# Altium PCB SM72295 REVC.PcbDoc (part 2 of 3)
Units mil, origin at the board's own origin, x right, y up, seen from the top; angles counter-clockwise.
Board outline 8660 x 6340 mil, 6 copper layers (Top Layer, MidLayer1, MidLayer2, MidLayer3, MidLayer4, Bottom Layer), stack 118 mil thick; 253 components, 96 nets, 606 pads, 1472 vias.
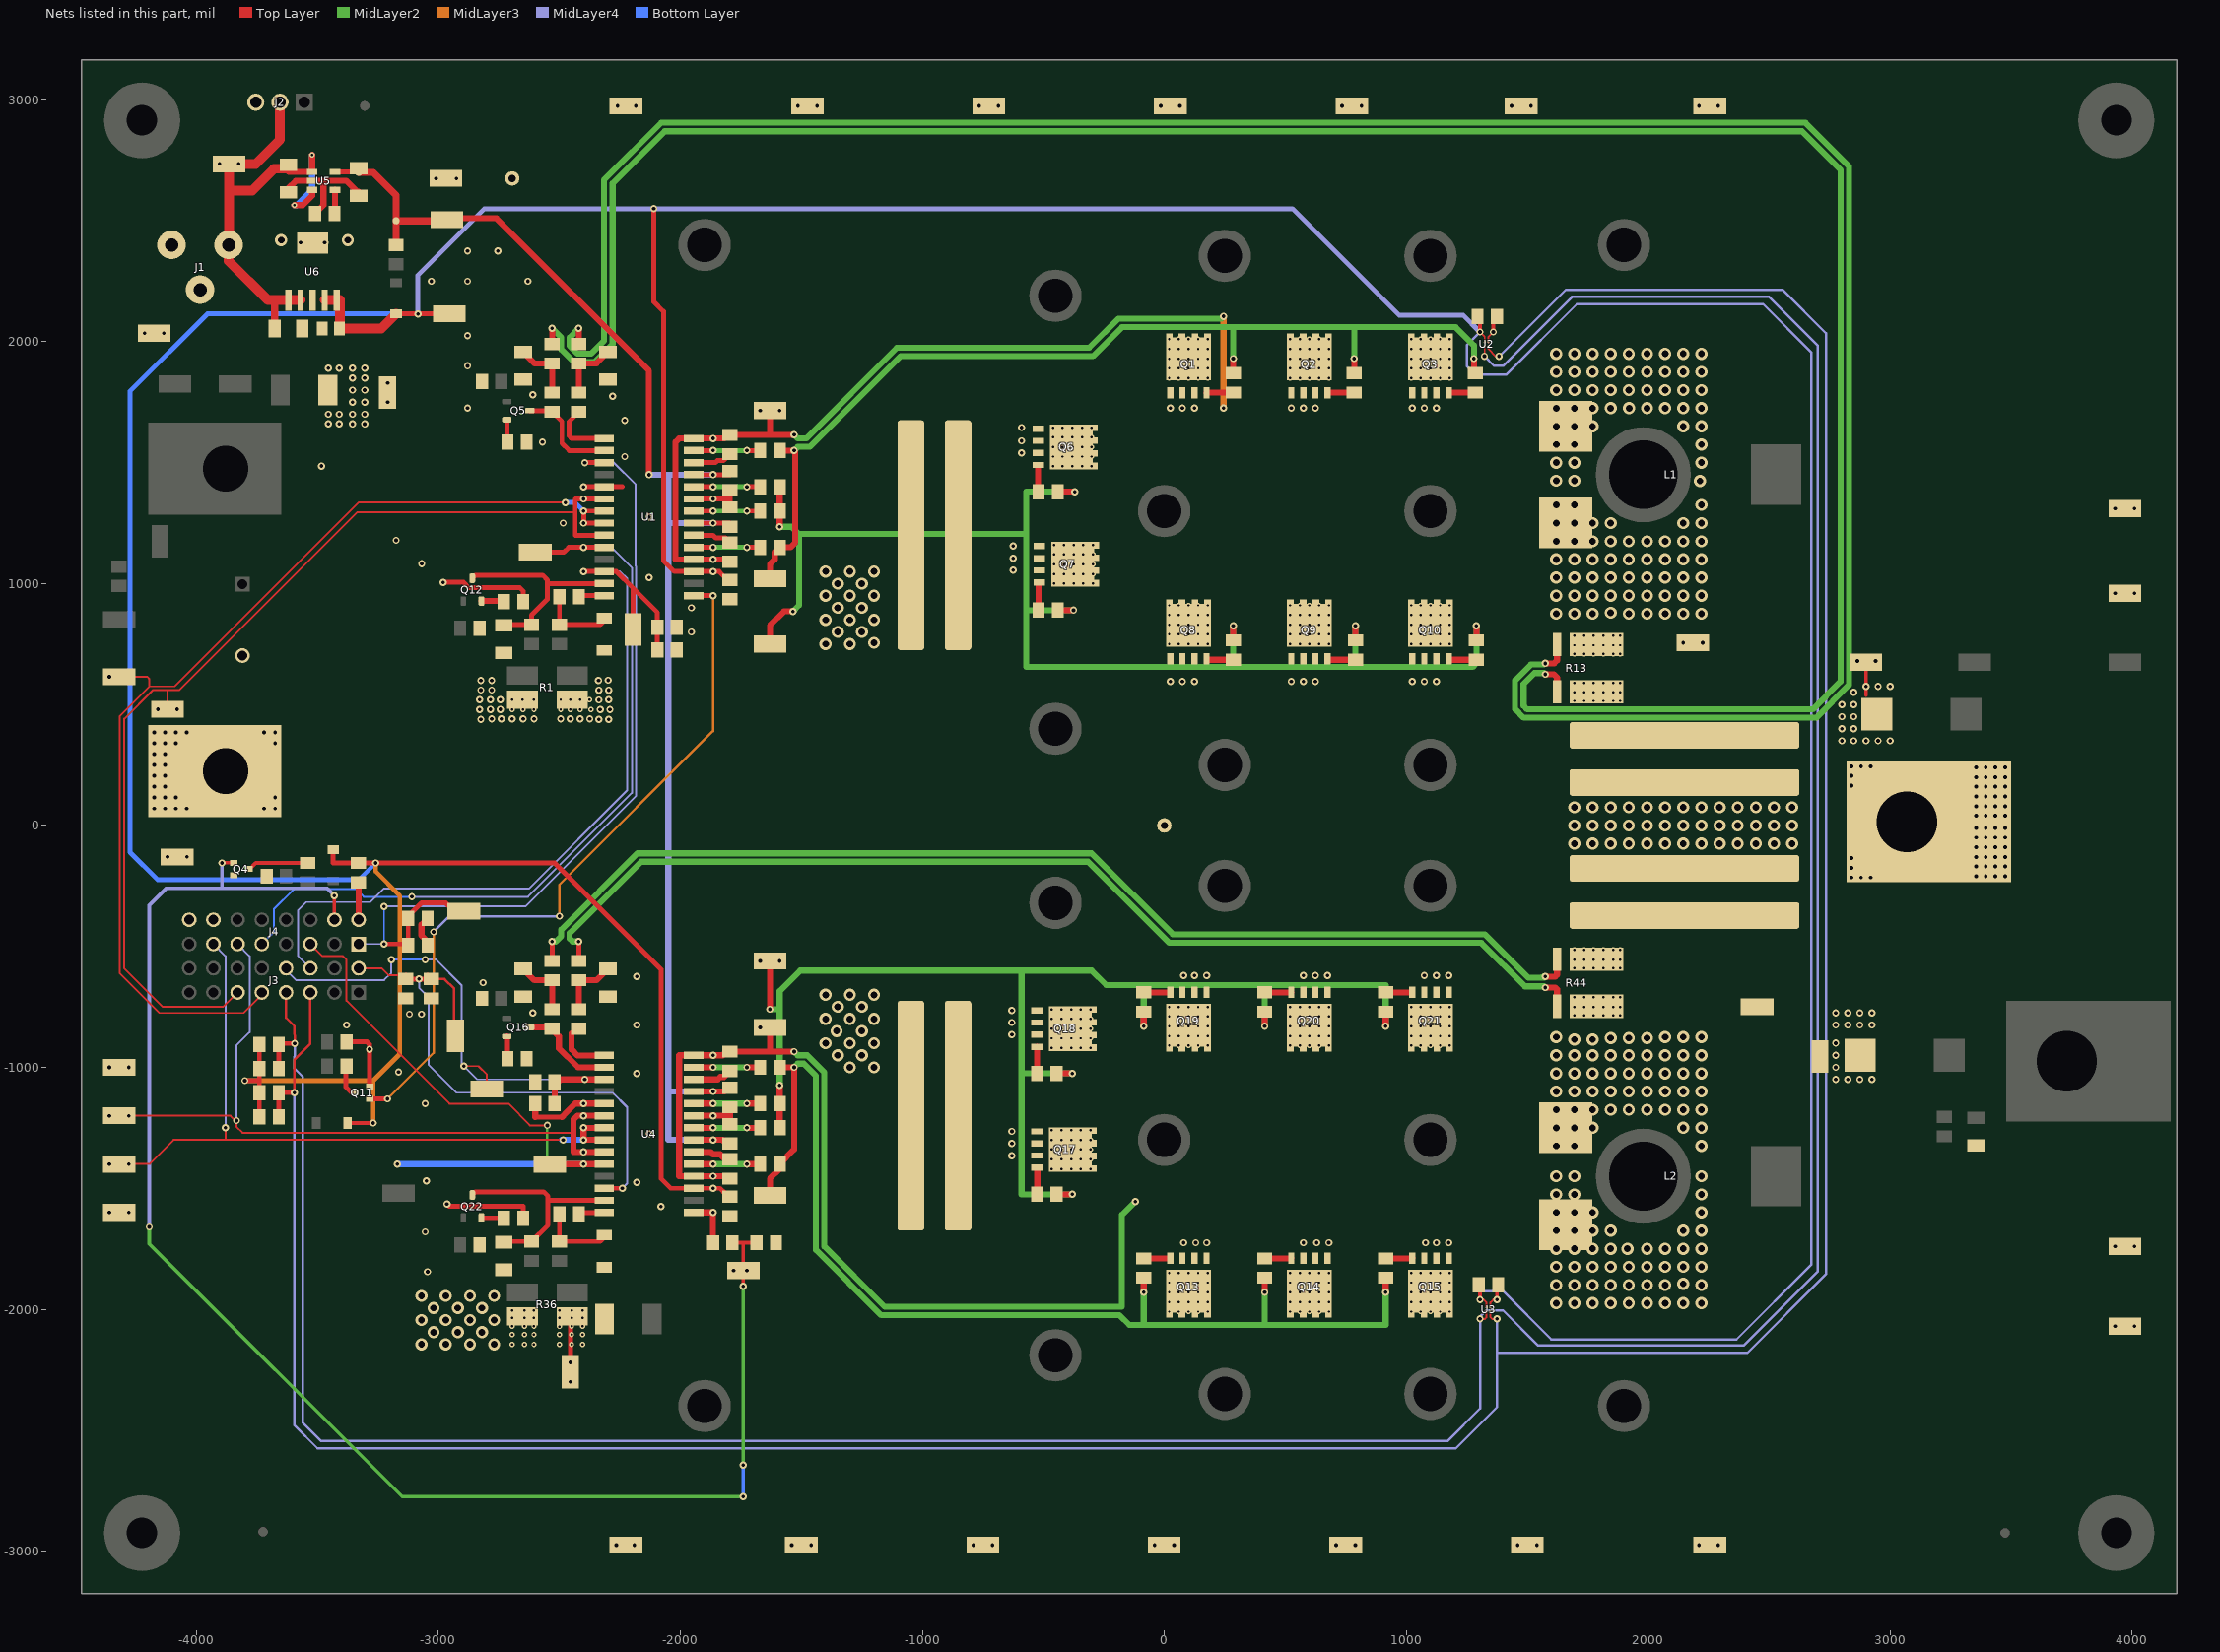
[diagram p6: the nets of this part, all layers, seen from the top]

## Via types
v1: diameter 22, hole 10, Top Layer to Bottom Layer, 518 vias
v2: diameter 30, hole 15, Top Layer to Bottom Layer, 479 vias
v3: diameter 50, hole 28, Top Layer to Bottom Layer, 303 vias
v4: diameter 32, hole 16, Top Layer to Bottom Layer, 172 vias

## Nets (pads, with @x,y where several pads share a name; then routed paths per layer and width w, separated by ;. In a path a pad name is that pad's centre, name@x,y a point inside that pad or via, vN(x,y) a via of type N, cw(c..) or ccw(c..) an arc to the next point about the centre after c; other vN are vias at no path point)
3.3V: C5.1 C11.1 C14.1 C27.1 C35.1 D1.1 D2.1 D3.1 R9.1 R10.1 R18.1 R19.1 R30.2 TP36.1 U1.17 U2.A1 U3.A1 U4.17 U6.4 U6.5 | length 23986.5
  Top Layer w6: C5.1@1297.95,2096.57 C5.1@1301.46,2100.08
  Top Layer w8: v2(1305,-1960) 1320,-1960 1332.13,-1972.13 U3.A1@1332.13,-1992.13 ; C11.1@1305,-1913.5 C11.1@1308.5,-1910 ; v2(1305,2040) 1324.25,2020.75 U2.A1@1324.25,1997.87
  Top Layer w15: v2(1305,-1960) C11.1@1305,-1913.5 ; v2(1305,2040) C5.1@1305,2095
  Top Layer w17.72: D2.1@-3375.53,-1230 v2(-3270,-1230)
  Top Layer w20: v2(-3800,-1055) -3740,-1055 ; R9.1@-3740,-1205 R18.1@-3740,-1105 -3740,-1055 ; R10.1@-3740,-1005 R19.1@-3740,-905 ; R10.1@-3735,-990 -3736.02,-1005.27 -3740,-1009.25 -3740,-1055 ; D1.1@-3435,-100.53 -3435,-155 R30.2@-3330,-155 v2(-3260,-155) -2520,-155 -2080,-595 -2080,-1460 -2040,-1500 U4.17@-1945,-1500 v2(-1865,-1500) -1836.47,-1500 C27.1@-1812.85,-1523.62 ; D3.1@-3175.53,2115 v2(-3085,2115) TP36.1@-2955,2115 ; v2(-2110,2550) -2110,2165 -2070,2125 -2070,1095 -2025,1050 U1.17@-1945,1050 ; U1.17@-1950,1045 U1.17@-1945,1050 ; C14.1@-1795,1015 -1805,1015 -1840,1050 v2(-1865,1050) U1.17@-1945,1050
  Top Layer w25: C27.1@-1812.85,-1523.62 C27.1@-1795,-1523.62
  Top Layer w40: U6.4@-3470,2171.89 U6.5@-3420,2171.89 -3406.89,2171.89 -3406.89,2056.89 -3405,2055 -3235.53,2055 -3175.53,2115 D3.1@-3175,2115.53
  MidLayer3 w17.72: v2(-3270,-1230) -3270,-1055 ; v2(-3260,-155) -3260,-190 -3160,-290 -3160,-935
  MidLayer3 w20: v2(-3800,-1055) -3270,-1055 -3160,-945 -3160,-935
  MidLayer4 w10: 1305,-1925 1400,-1925 1600,-2125 2365,-2125 2675,-1815 2675,1955 2475,2155 1705,2155 1413.13,1863.13 1286.87,1863.13 1250,1900 1250,1985 v2(1305,2040)
  MidLayer4 w15: v2(1305,-1960) 1305,-1925
  MidLayer4 w20: v2(-3085,2115) -3085,2275 -2810,2550 530,2550 970,2110 1235,2110 v2(1305,2040)
  Bottom Layer w17.72: -3335,-225 -3330,-225 v2(-3260,-155)
  Bottom Layer w20: -3335,-225 -4160,-225 -4275,-110 -4275,1795 -3955,2115 v2(-3085,2115)
10V: C7.1 C10.1 C23.1 C25.1 C30.1 pad.EndPad pad.StartPad R58.1 TP34.1 U1.21 U1.25 U4.21 U4.25 U5.5 | length 6359.7
  Top Layer w20: U5.5@-3427.76,2702.4 pad.StartPad@-3332.4,2702.4 ; U1.21@-1945,1250 v2(-1865,1250) C10.1@-1795.43,1250 ; U1.25@-1945,1450 v2(-1865,1450) -1795.43,1450 C7.1@-1795,1450.43
  Top Layer w25: TP34.1@-2934.59,2510.41 -2760.41,2510.41 -2130,1880 v2(-2130,1450) ; U4.21@-1945,-1300 v2(-1865,-1300) -1825,-1300 C25.1@-1805,-1320 ; U4.25@-1945,-1100 v2(-1865,-1100) -1820,-1100 C23.1@-1810,-1090
  Top Layer w30: pad.StartPad@-3330,2700 -3270,2700 -3175,2605 pad.EndPad@-3175,2500 ; R58.1@-3175,2400 pad.EndPad@-3175,2500 ; TP34.1@-2965,2505 -2970,2500 pad.EndPad@-3175,2500
  MidLayer4 w25: v2(-2130,1450) -2050,1450 ; v2(-1865,-1300) -2050,-1300 -2050,-1100 ; v2(-1865,-1100) -2050,-1100 ; v2(-1865,1250) -2050,1250 ; v2(-1865,1450) -2050,1450 ; -2050,-1100 -2050,1250 ; -2050,1250 -2050,1450
12V: C31.1 C36.1 J1.1 J2.2 TP35.1 U5.1 U5.3 U6.1 U6.2 | length 2084.8
  Top Layer w25.59: -3617.6,2702.4 U5.1@-3522.24,2702.4 v1(-3522.24,2772.76) ; v1(-3595,2565) -3560.73,2565 -3522.24,2603.49 U5.3@-3522.24,2627.6
  Top Layer w30: C36.1@-3677.09,2055 -3677.09,2154.8
  Top Layer w40: J1.1@-3866.89,2400 -3866.89,2333.39 -3705.39,2171.89 -3660,2171.89 U6.1@-3620,2171.89 U6.2@-3570,2171.89 ; J1.1@-3865,2391.5 -3865,2625 ; J2.2@-3655,2990 -3655,2835 -3755,2735 TP35.1@-3865,2735 -3865,2625 ; C31.1@-3620,2715 -3680,2715 -3770,2625 -3865,2625
  Bottom Layer w25.59: v1(-3595,2565) -3584.84,2565 -3522.24,2627.6 v1(-3522.24,2772.76)
  other v2: -3905,2735 -3825,2735
\O\V\P: C41.2 J4.4 Q4.1 R59.1 TP15.1 | length 6497.9
  Top Layer w15: v2(-3895,-155) -3894.41,-154.41 Q4.1@-3846.5,-154.41 ; J4.4@-3430,-390 v2(-3430,-290) ; R59.1@-1785,-1725 -1740,-1725 ; v2(-1740,-1905) TP15.1@-1740,-1840 -1740,-1725 ; C41.2@-1685,-1725 -1740,-1725
  MidLayer2 w15: v2(-4195,-1660) -4195,-1730 -3150,-2775 v2(-1740,-2775) ; v2(-1740,-2645) v2(-1740,-1905)
  MidLayer4 w15: v2(-4195,-1660) -4195,-330 -4124.32,-259.32 -3895,-259.32 ; v2(-3895,-155) -3895,-259.32 ; v2(-3430,-290) -3460.68,-259.32 -3880,-259.32 -3895,-259.32
  Bottom Layer w15: v2(-1740,-2775) v2(-1740,-2645)
  other v2: -1780,-1840 -1725,-1840
\O\V\P\_\1\2: R59.2 U4.15 | length 200
  Top Layer w25: U4.15@-1945,-1600 v2(-1865,-1600) R59.2@-1865,-1720
\O\V\P\_\4\8: Q11.1 U1.15 | length 3057.4
  Top Layer w20: Q11.1@-3283.5,-1130.59 v2(-3210.59,-1130.59) ; U1.15@-1945,950 v2(-1865,950)
  MidLayer3 w10: v2(-3210.59,-1130.59) -3020,-940 v2(-3020,-440) ; v2(-2500,-375) -2500,-245 -1865,390 v2(-1865,950)
  MidLayer4 w10: v2(-3020,-440) -2955,-375 v2(-2500,-375)
GND: C1.1 C2.2 C3.1 C4.2 C5.2 C7.2 C8.1 C9.2 C10.2 C11.2 C13.2 C14.2 C15.2 C16.2 C17.2 C18.2 C19.1 C20.1 C21.2 C23.2 C24.1 C25.2 C27.2 C28.2 C29.2 C30.2 C31.2 C32.2 C33.2 C35.2 C36.2 C37.2 C38.2 C39.1 C40.1 C41.1 C42.2 J1.2 J1.3 J2.3 J4.14 J4.16 pad.0 Q4.2 Q6.1 Q6.2 Q6.3 Q7.1 Q7.2 Q7.3 Q8.1 Q8.2 Q8.3 Q9.1 Q9.2 Q9.3 Q10.1 Q10.2 Q10.3 Q11.2 Q17.1 Q17.2 Q17.3 Q18.1 Q18.2 Q18.3 Q19.1 Q19.2 Q19.3 Q20.1 Q20.2 Q20.3 Q21.1 Q21.2 Q21.3 R11.1 R16.1 R27.1 R31.1 R33.1 R34.1 R35.1 R42.1 R61.1 T2.1 T4.1 TP5.1 TP11.1 TP33.1 TP37.1 TP38.1 TP39.1 TP40.1 TP41.1 TP42.1 TP43.1 TP44.1 TP45.1 TP46.1 TP47.1 TP48.1 TP49.1 TP50.1 TP51.1 TP52.1 TP53.1 TP54.1 TP55.1 TP56.1 U1.5 U1.23 U2.A2 U3.A2 U4.5 U4.23 U5.2 U6.3 U6.6 | length 2814
  Top Layer w8: U2.A2@1340,1997.87 1340,2020 v2(1360,2040) ; U3.A2@1347.87,-1992.13 1347.87,-1972.13 1360,-1960 v2(1375,-1960) ; C5.2@1364.45,2100.08 1367.26,2097.26 C5.2@1367.95,2096.57 ; C11.2@1371.5,-1910 C11.2@1375,-1913.5
  Top Layer w15: v2(1360,2040) 1360,2090 1367.26,2097.26 C5.2@1375,2105 ; v2(1375,-1960) C11.2@1375,-1913.5
  Top Layer w20: C9.2@-3380,-895 -3295,-895 -3285,-905 v2(-3285,-925) Q11.2@-3285,-1079.41 ; v2(-2980,1005) -2896.07,1005 -2874.07,983 -2663,983 -2650,970 R33.1@-2650,925 ; v2(-2965,-1565) -2955,-1575 -2650,-1575 R61.1@-2650,-1625 ; -2600,-1205 -2490,-1205 ; v2(-2400,1400) U1.5@-2315,1400 -2240,1400 ; U1.23@-1945,1350 v2(-1865,1350) -1795,1350 ; C10.2@-1795,1320.43 -1795,1350 ; C7.2@-1795,1379.57 -1795,1350
  Top Layer w25: C31.2@-3620,2635 -3590,2665 U5.2@-3522.24,2665 -3475,2665 ; C29.2@-3510,2530 -3475.37,2564.63 -3475.37,2664.63 -3475,2665 ; C30.2@-3330,2620 -3335.31,2620 -3380.31,2665 -3475,2665 ; R31.1@-3045,-495 -3045,-480 -3070,-455 -3070,-410 C37.2@-3045,-385 ; -2600,-1205 C38.2@-2600,-1150 ; -2490,-1205 -2486.87,-1201.87 -2486.56,-1201.87 -2474.63,-1189.94 -2474.63,-1189.63 -2435,-1150 v2(-2400,-1150) U4.5@-2315,-1150 ; U4.23@-1945,-1200 v2(-1865,-1200) -1795,-1200 ; C23.2@-1795,-1170.43 -1795,-1200 ; C25.2@-1785.87,-1229.57 -1795,-1229.57 -1795,-1200
  other v2: -2265,-2975 -2190,-2975 -1540,-2975 -1460,-2975 -790,-2975 -710,-2975 -40,-2975 40,-2975 710,-2975 790,-2975 1460,-2975 1540,-2975 2210,-2975 2290,-2975 3930,-2070 4010,-2070 -3045,-1845 3930,-1740 4010,-1740 -3055,-1680 -4360,-1600 -4280,-1600 -2080,-1575 -2180,-1475 -3050,-1470 -630,-1365 -630,-1315 -2130,-1275 -630,-1265 -3055,-1150 -2180,-1025 -3165,-1020 -4360,-1000 -4280,-1000 -630,-865 -3380,-825 -2180,-825 -630,-815 -3120,-780 -3070,-780 -2610,-775 -630,-765 -2815,-650 -2180,-625 80,-620 125,-620 175,-620 575,-620 625,-620 675,-620 1075,-620 1125,-620 1175,-620 -4120,-130 -4040,-130 25,595 75,595 125,595 525,595 575,595 625,595 1025,595 1075,595 1125,595 -1955,800 -1955,900 3930,960 4010,960 -2130,1025 -625,1055 -3069,1082 -625,1105 -625,1155 -3175,1179 -2485,1250 -2130,1275 3930,1310 4010,1310 -3483,1486 -2230,1525 -590,1540 -2570,1585 -590,1590 -590,1645 -2230,1675 -2880,1725 -2280,1775 -2610,1780 -2880,1900 -2880,2025 -4215,2035 -4135,2035 -3030,2250 -2880,2250 -2630,2250 -2880,2375 -2755,2375 -3570,2410 -3470,2410 -3010,2675 -2925,2675 -2260,2975 -2185,2975 -1515,2975 -1435,2975 -765,2975 -685,2975 -15,2975 65,2975 735,2975 815,2975 1435,2975 1515,2975 2210,2975 2290,2975
  other v3: 1695,-75 1770,-75 1845,-75 1920,-75 1995,-75 2070,-75 2145,-75 2220,-75 2295,-75 2370,-75 2445,-75 2520,-75 2595,-75 1695,0 1770,0 1845,0 1920,0 1995,0 2070,0 2145,0 2220,0 2295,0 2370,0 2445,0 2520,0 2595,0 1695,75 1770,75 1845,75 1920,75 1995,75 2070,75 2145,75 2220,75 2295,75 2370,75 2445,75 2520,75 2595,75 -3650,2420 -3375,2420
  other v4: 2840,-215 2880,-215 2920,-215 3355,-210 3395,-210 3435,-210 3475,-210 2840,-175 3355,-170 3395,-170 3435,-170 3475,-170 2840,-135 3355,-130 3395,-130 3435,-130 3475,-130 3355,-90 3395,-90 3435,-90 3475,-90 3355,-50 3395,-50 3435,-50 3475,-50 3355,-10 3395,-10 3435,-10 3475,-10 3355,40 3395,40 3435,40 3475,40 -4175,70 -4130,70 -4085,70 -4040,70 -3720,70 -3675,70 3355,80 3395,80 3435,80 3475,80 -4175,115 -4130,115 -4085,115 -3675,115 3355,120 3395,120 3435,120 3475,120 -4175,160 -4130,160 3355,160 3395,160 3435,160 3475,160 2840,165 3355,200 3395,200 3435,200 3475,200 -4175,205 -4130,205 2840,205 3355,240 3395,240 3435,240 3475,240 2840,245 2880,245 2920,245 -4175,250 -4130,250 -4175,295 -4130,295 -4175,340 -4130,340 -4085,340 -3675,340 -4175,385 -4130,385 -4085,385 -4040,385 -3720,385 -3675,385
HG1A_N: C6.1 C12.1 L1.1 Q1.1 Q1.2 Q1.3 Q2.1 Q2.2 Q2.3 Q3.1 Q3.2 Q3.3 Q6.5 Q6.6 Q6.7 Q6.8 Q6.9 Q7.5 Q7.6 Q7.7 Q7.8 Q7.9 Q8.5 Q8.6 Q8.7 Q8.8 Q8.9 Q9.5 Q9.6 Q9.7 Q9.8 Q9.9 Q10.5 Q10.6 Q10.7 Q10.8 Q10.9 TP6.1 U1.18 U1.28 | length 3672.8
  Top Layer w25: C6.1@-1805,1615 -1820,1600 v2(-1865,1600) U1.28@-1945,1600 -2005,1600 -2020,1585 -2020,1100 U1.18@-1945,1100 v2(-1865,1100) C12.1@-1795,1100 ; C6.1@-1795,1615 -1630,1615 ; TP6.1@-1630,1715 -1630,1615 ; v2(-1530,1615) -1630,1615
  MidLayer2 w25: v2(-1530,1615) -1515,1600 -1480,1600 -1105,1975 -310,1975 -190,2095 235,2095 v2(245,2105)
  MidLayer3 w25: v2(245,1725) v2(245,2105)
  other v1: 20,750 60,750 100,750 140,750 180,750 520,750 560,750 600,750 640,750 680,750 1020,750 1060,750 1100,750 1140,750 1180,750 20,790 60,790 100,790 140,790 180,790 520,790 560,790 600,790 640,790 680,790 1020,790 1060,790 1100,790 1140,790 1180,790 20,830 60,830 100,830 140,830 180,830 520,830 560,830 600,830 640,830 680,830 1020,830 1060,830 1100,830 1140,830 1180,830 20,870 60,870 100,870 140,870 180,870 520,870 560,870 600,870 640,870 680,870 1020,870 1060,870 1100,870 1140,870 1180,870 20,910 60,910 100,910 140,910 180,910 520,910 560,910 600,910 640,910 680,910 1020,910 1060,910 1100,910 1140,910 1180,910 -455,1000 -415,1000 -375,1000 -335,1000 -295,1000 -455,1040 -415,1040 -375,1040 -335,1040 -295,1040 -455,1080 -415,1080 -375,1080 -335,1080 -295,1080 -455,1120 -415,1120 -375,1120 -335,1120 -295,1120 -455,1160 -415,1160 -375,1160 -335,1160 -295,1160 -460,1485 -420,1485 -380,1485 -340,1485 -300,1485 -460,1525 -420,1525 -380,1525 -340,1525 -300,1525 -460,1565 -420,1565 -380,1565 -340,1565 -300,1565 -460,1605 -420,1605 -380,1605 -340,1605 -300,1605 -460,1645 -420,1645 -380,1645 -340,1645 -300,1645
  other v2: -1670,1715 -1590,1715 25,1725 75,1725 125,1725 525,1725 575,1725 625,1725 1025,1725 1075,1725 1125,1725
  other v3: 2214.32,1424 1620,1425 1695,1425 1620,1500 1695,1500 2220,1500 1620,1575 1695,1575 2220,1575 1620,1650 1695,1650 1770,1650 2145,1650 2220,1650 1620,1725 1695,1725 1770,1725 1845,1725 1921.19,1725 1995,1725 2070,1725 2145,1725 2220,1725 1620,1800 1695,1800 1770,1800 1845,1800 1920,1800 1995,1800 2070,1800 2145,1800 2220,1800 1620,1875 1695,1875 1770,1875 1845,1875 1920,1875 1995,1875 2070,1875 2145,1875 2220,1875 1620,1950 1695,1950 1770,1950 1845,1950 1920,1950 1995,1950 2070,1950 2145,1950 2220,1950
HG1A_P: R4.1 R5.2 R6.2 R12.2 R26.2 TP4.1 | length 4206.3
  Top Layer w25: TP4.1@-1635,1020 -1630,1025 -1630,1080 -1610,1100 -1610,1130 R26.2@-1590,1150 -1545,1150 -1525,1170 -1525,1545 v2(-1530,1550) R12.2@-1590,1550 ; R4.1@285,1870 v2(285,1930) ; R5.2@785,1870 v2(785,1930) ; R6.2@1280,1875 v2(1280,1930)
  MidLayer2 w25: v2(-1530,1550) -1515,1565 -1465.5,1565 -1090.5,1940 -295.5,1940 -175.5,2060 285,2060 ; v2(285,1930) 285,2060 ; v2(785,1930) 785,2060 ; v2(1280,1930) 1280,1985 1205,2060 785,2060 ; 285,2060 785,2060
HG2A_N: C22.1 C26.1 L2.2 Q13.1 Q13.2 Q13.3 Q14.1 Q14.2 Q14.3 Q15.1 Q15.2 Q15.3 Q17.5 Q17.6 Q17.7 Q17.8 Q17.9 Q18.5 Q18.6 Q18.7 Q18.8 Q18.9 Q19.5 Q19.6 Q19.7 Q19.8 Q19.9 Q20.5 Q20.6 Q20.7 Q20.8 Q20.9 Q21.5 Q21.6 Q21.7 Q21.8 Q21.9 TP28.1 U4.18 U4.28 | length 3943.5
  Top Layer w25: C22.1@-1810,-935 -1825,-950 v2(-1865,-950) U4.28@-1945,-950 -2005,-950 -2005.38,-950.38 -2005.38,-1450 U4.18@-1945,-1450 v2(-1865,-1450) C26.1@-1795,-1450 ; C22.1@-1795,-935 v2(-1530,-935) ; -1630,-930.49 TP28.1@-1630,-835
  MidLayer2 w25: v2(-1530,-935) -1515,-950 -1475.5,-950 -1405,-1020.5 -1405,-1740 -1155,-1990 -175,-1990 -175,-1610 v2(-120,-1555)
  other v1: -465,-1420 -425,-1420 -385,-1420 -345,-1420 -305,-1420 -465,-1380 -425,-1380 -385,-1380 -345,-1380 -305,-1380 -465,-1340 -425,-1340 -385,-1340 -345,-1340 -305,-1340 -465,-1300 -425,-1300 -385,-1300 -345,-1300 -305,-1300 -465,-1260 -425,-1260 -385,-1260 -345,-1260 -305,-1260 -465,-920 -425,-920 -385,-920 -345,-920 -305,-920 20,-910 60,-910 100,-910 140,-910 180,-910 520,-910 560,-910 600,-910 640,-910 680,-910 1020,-910 1060,-910 1100,-910 1140,-910 1180,-910 -465,-880 -425,-880 -385,-880 -345,-880 -305,-880 20,-870 60,-870 100,-870 140,-870 180,-870 520,-870 560,-870 600,-870 640,-870 680,-870 1020,-870 1060,-870 1100,-870 1140,-870 1180,-870 -465,-840 -425,-840 -385,-840 -345,-840 -305,-840 20,-830 60,-830 100,-830 140,-830 180,-830 520,-830 560,-830 600,-830 640,-830 680,-830 1020,-830 1060,-830 1100,-830 1140,-830 1180,-830 -465,-800 -425,-800 -385,-800 -345,-800 -305,-800 20,-790 60,-790 100,-790 140,-790 180,-790 520,-790 560,-790 600,-790 640,-790 680,-790 1020,-790 1060,-790 1100,-790 1140,-790 1180,-790 -465,-760 -425,-760 -385,-760 -345,-760 -305,-760 20,-750 60,-750 100,-750 140,-750 180,-750 520,-750 560,-750 600,-750 640,-750 680,-750 1020,-750 1060,-750 1100,-750 1140,-750 1180,-750
  other v2: 80,-1725 130,-1725 175,-1725 575,-1725 630,-1725 680,-1725 1080,-1725 1125,-1725 1175,-1725 -1670,-835
  other v3: 1620,-1975 1695,-1975 1770,-1975 1845,-1975 1920,-1975 1995,-1975 2070,-1975 2145,-1975 2220,-1975 1620,-1900 1695,-1900 1770,-1900 1845,-1900 1920,-1900 1995,-1900 2070,-1900 2220,-1900 2145,-1895 1620,-1825 1695,-1825 1770,-1825 1845,-1825 1920,-1825 1995,-1825 2070,-1825 2145,-1825 2220,-1825 1620,-1750 1695,-1750 1770,-1750 1845,-1750 1914.21,-1750 1995,-1750 2070,-1750 2145,-1750 2220,-1750 1620,-1675 1695,-1675 1770,-1675 1845,-1675 2145,-1675 2220,-1675 1620,-1600 1695,-1600 1770,-1600 2220,-1600 1620,-1525 1695,-1525 2220,-1525 1620,-1450 1695,-1450 2220,-1450
HG2A_P: R37.2 R38.2 R41.1 R43.2 R52.2 TP27.1 | length 4538.5
  Top Layer w25: TP27.1@-1635,-1530 -1630,-1525 -1630,-1460 -1590,-1420 R52.2@-1590,-1400 -1530,-1340 v2(-1530,-1000) R43.2@-1590,-1000 ; v2(-85,-1930) R41.1@-85,-1870 ; v2(415,-1930) R37.2@415,-1870 ; v2(915,-1930) R38.2@915,-1870
  MidLayer2 w25: v2(-1530,-1000) -1515,-985 -1490,-985 -1440,-1035 -1440,-1754.5 -1169.5,-2025 -185,-2025 -145,-2065 -85,-2065 ; v2(-85,-1930) -85,-2065 ; v2(415,-1930) 415,-2065 ; v2(915,-1930) 915,-2065 415,-2065 ; -85,-2065 415,-2065
IL1M: C37.1 J4.1 R31.2 TP13.1 U1.3 | length 3575.8
  Top Layer w8: R31.2@-3130,-490 R31.2@-3125,-495
  Top Layer w20: v2(-3225,-490) R31.2@-3130,-490 ; R31.2@-3125,-495 C37.1@-3125,-405 ; C37.1@-3125,-385 -3125,-374.97 -3070.03,-320 -2970,-320 -2935,-355 TP13.1@-2895,-355 ; v2(-2395,1500) U1.3@-2315,1500
  MidLayer4 w8: J4.1@-3330,-490 v2(-3225,-490) ; v2(-3225,-335) -2640,-335 -2184.13,120.87 -2184.13,1071.58 -2185,1072.45 -2185,1410 -2275,1500 v2(-2395,1500)
  Bottom Layer w8: v2(-3225,-490) v2(-3225,-335)
IL2M: C38.1 J3.8 R35.2 TP19.1 U4.3 | length 2199.7
  Top Layer w8: v2(-2895,-995) -2835,-995 -2800,-1030 TP19.1@-2800,-1090
  Top Layer w25: C38.1@-2520,-1150 R35.2@-2520,-1060 ; R35.2@-2500,-1055 -2495,-1050 v2(-2395,-1050) U4.3@-2315,-1050
  MidLayer2 w8: J3.8@-3650,-590 J3.8@-3630,-590
  MidLayer4 w8: J3.8@-3630,-585 J3.8@-3630,-590 ; J3.8@-3625,-590 J3.8@-3630,-590 ; v2(-3195,-555) -3195,-610 -3224.37,-639.37 -3589.37,-639.37 -3630,-598.75 J3.8@-3630,-590 ; v2(-3055,-555) -3010,-555 -2905,-660 -2905,-985 -2840,-1050 v2(-2395,-1050)
  Bottom Layer w8: v2(-3195,-555) v2(-3055,-555)
LG1A: R15.2 R20.2 R21.2 R22.2 R23.2 R24.2 R25.1 TP10.1 | length 5500
  Top Layer w25: TP10.1@-1630,750 -1630,827 -1572,885 v2(-1535,885) ; v2(-1590,1235) R20.2@-1590,1300 R15.2@-1590,1400 ; R22.2@-440,890 v2(-375,890) ; R25.1@-440,1380 v2(-370,1380) ; R23.2@285,765 v2(285,825) ; R21.2@790,765 v2(790,825) ; R24.2@1290,770 v2(1290,825)
  MidLayer2 w25: v2(-1590,1235) -1540,1235 -1510,1205 ; v2(-1535,885) -1510,910 -1510,1205 ; -555,890 v2(-375,890) ; v2(-370,1380) -570,1380 -570,1205 ; 285,655 v2(285,825) ; 790,655 v2(790,825) ; v2(1290,825) 1290,670 1275,655 -570,655 -570,1205 ; -1510,1205 -570,1205
LG2A: R45.2 R46.2 R47.2 R48.2 R49.2 R50.2 R51.2 TP32.1 | length 5532.1
  Top Layer w25: v2(-1630,-760) TP32.1@-1630,-563 ; R46.2@-1590,-1250 R45.2@-1590,-1150 v2(-1590,-1075) ; R51.2@-445,-1525 v2(-380,-1525) ; R47.2@-445,-1025 v2(-380,-1025) ; v2(-85,-830) R48.2@-85,-770 ; v2(415,-830) R49.2@415,-770 ; v2(915,-830) R50.2@915,-770
  MidLayer2 w25: v2(-1630,-760) -1590,-760 ; v2(-1590,-1075) -1590,-760 ; v2(-380,-1525) -590,-1525 -590,-1025 ; v2(-380,-1025) -590,-1025 ; v2(-85,-830) -85,-660 ; v2(415,-830) 415,-660 ; v2(915,-830) 915,-660 415,-660 ; -1590,-760 -1590,-685 -1505,-600 -590,-600 ; -590,-1025 -590,-600 ; -590,-600 -300,-600 -240,-660 -85,-660 ; -85,-660 415,-660
  other v2: -1670,-560 -1590,-560
NetC1_2: C1.2 Q1.5 Q1.6 Q1.7 Q1.8 Q1.9 Q2.5 Q2.6 Q2.7 Q2.8 Q2.9 Q3.5 Q3.6 Q3.7 Q3.8 Q3.9 R1.1
  other v1: -2695,480 -2650,480 -2605,480 -2695,520 -2605,520 -2653.35,520.79 20,1850 60,1850 100,1850 140,1850 180,1850 520,1850 560,1850 600,1850 640,1850 680,1850 1020,1850 1060,1850 1100,1850 1140,1850 1180,1850 20,1890 60,1890 100,1890 140,1890 180,1890 520,1890 560,1890 600,1890 640,1890 680,1890 1020,1890 1060,1890 1100,1890 1140,1890 1180,1890 20,1930 60,1930 100,1930 140,1930 180,1930 520,1930 560,1930 600,1930 640,1930 680,1930 1020,1930 1060,1930 1100,1930 1140,1930 1180,1930 20,1970 60,1970 100,1970 140,1970 180,1970 520,1970 560,1970 600,1970 640,1970 680,1970 1020,1970 1060,1970 1100,1970 1140,1970 1180,1970 20,2010 60,2010 100,2010 140,2010 180,2010 520,2010 560,2010 600,2010 640,2010 680,2010 1020,2010 1060,2010 1100,2010 1140,2010 1180,2010
  other v2: -2825,438.96 -2780,440 -2740,440 -2695,440 -2650,440 -2605,440 -2830,479.31 -2785,480 -2745,480 -2830,519.65 -2785,520 -2745,519.65 -2825,560 -2780,560 -2825,600 -2780,600
  other v3: -1400,750 -1300,750 -1200,755 -1350,800 -1250,800 -1400,850 -1300,850 -1200,850 -1350,900 -1250,900 -1400,950 -1300,950 -1200,950 -1350,1000 -1250,1000 -1400,1050 -1300,1050 -1200,1050
NetC3_2: C3.2 R7.1 R63.2 | length 259.5
  Top Layer w25: C3.2@-2650,1957.09 -2602.91,1910 R7.1@-2530,1910 R63.2@-2530,1790
NetC6_2: C6.2 U1.26 | length 164.5
  Top Layer w20: U1.26@-1945,1500 -1855,1500 -1847.13,1507.87 -1822.13,1507.87 C6.2@-1795,1535
NetC8_2: C8.2 F2.2 R13.1 TP8.1 | length 135.9
  Top Layer w15: 2900,539.06 v2(2900,575) TP8.1@2900,675
  other v1: 1695,515 1735,515 1775,515 1815,515 1855,515 1885,515 1695,550 1735,550 1775,550 1815,550 1855,550 1885,550 1695,590 1735,590 1775,590 1815,590 1855,590 1885,590
  other v2: 2800,350 2850,350 2900,350 2950,350 3000,350 2800,400 2850,400 2800,450 2850,450 2800,500 2850,500 2850,550 2950,575 3000,575 2865,680 2940,680
NetC12_2: C12.2 U1.20 | length 162.4
  Top Layer w20: U1.20@-1945,1200 -1865.59,1200 -1854.56,1188.97 -1813.97,1188.97 C12.2@-1795,1170
NetC15_1: C15.1 R28.1 R29.2 | length 307.1
  Top Layer w20: R29.2@-2500,945 R28.1@-2500,830 -2332.09,830 C15.1@-2315,847.09
NetC19_2: C19.2 Q13.5 Q13.6 Q13.7 Q13.8 Q13.9 Q14.5 Q14.6 Q14.7 Q14.8 Q14.9 Q15.5 Q15.6 Q15.7 Q15.8 Q15.9 R36.1 | length 0
  other v1: -2695,-2145 -2645,-2145 -2605,-2145 -2695,-2105 -2645,-2105 -2605,-2105 -2695,-2070 -2645,-2070 -2605,-2070 -2695,-2035 -2645,-2035 -2605,-2035 20,-2010 60,-2010 100,-2010 140,-2010 180,-2010 520,-2010 560,-2010 600,-2010 640,-2010 680,-2010 1020,-2010 1060,-2010 1100,-2010 1140,-2010 1180,-2010 -2695,-2005 -2645,-2005 -2605,-2005 20,-1970 60,-1970 100,-1970 140,-1970 180,-1970 520,-1970 560,-1970 600,-1970 640,-1970 680,-1970 1020,-1970 1060,-1970 1100,-1970 1140,-1970 1180,-1970 20,-1930 60,-1930 100,-1930 140,-1930 180,-1930 520,-1930 560,-1930 600,-1930 640,-1930 680,-1930 1020,-1930 1060,-1930 1100,-1930 1140,-1930 1180,-1930 20,-1890 60,-1890 100,-1890 140,-1890 180,-1890 520,-1890 560,-1890 600,-1890 640,-1890 680,-1890 1020,-1890 1060,-1890 1100,-1890 1140,-1890 1180,-1890 20,-1850 60,-1850 100,-1850 140,-1850 180,-1850 520,-1850 560,-1850 600,-1850 640,-1850 680,-1850 1020,-1850 1060,-1850 1100,-1850 1140,-1850 1180,-1850
  other v3: -3070,-2145 -2970,-2145 -2870,-2145 -2770,-2145 -3020,-2095 -2920,-2095 -2820,-2095 -3070,-2045 -2970,-2045 -2870,-2045 -2770,-2045 -3020,-1995 -2920,-1995 -2820,-1995 -3070,-1945 -2970,-1945 -2870,-1945 -2770,-1945 -1300,-1000 -1200,-1000 -1350,-950 -1250,-950 -1400,-900 -1300,-900 -1200,-900 -1355,-850 -1250,-850 -1400,-800 -1300,-800 -1200,-800 -1350,-750 -1250,-750 -1400,-700 -1300,-700 -1200,-700
NetC20_2: C20.2 R39.1 R65.2 | length 259.5
  Top Layer w25: C20.2@-2650,-592.91 -2602.91,-640 R39.1@-2530,-640 R65.2@-2530,-760
NetC22_2: C22.2 U4.26 | length 164.5
  Top Layer w25: U4.26@-1945,-1050 -1845.31,-1050 -1834.94,-1039.63 -1819.63,-1039.63 C22.2@-1795,-1015
NetC24_2: C24.2 F4.2 R44.2 TP30.1
  other v1: 1695,-590 1735,-590 1775,-590 1815,-590 1855,-590 1885,-590 1695,-555 1735,-555 1775,-555 1815,-555 1855,-555 1885,-555 1695,-515 1735,-515 1775,-515 1815,-515 1855,-515 1885,-515
  other v2: 2775,-1050 2825,-1050 2875,-1050 2925,-1050 2775,-1000 2775,-950 2775,-900 2775,-825 2825,-825 2875,-825 2925,-825 2775,-775 2825,-775 2875,-775 2925,-775
NetC26_2: C26.2 U4.20 | length 162.4
  Top Layer w25: U4.20@-1945,-1350 -1874.65,-1350 -1865,-1359.65 -1835.35,-1359.65 -1815,-1380 C26.2@-1795,-1380
NetC28_1: C28.1 R54.1 R55.2 | length 317.1
  Top Layer w20: R54.1@-2500,-1710 R54.1@-2500,-1720 ; R55.2@-2500,-1605 R54.1@-2500,-1720 ; C28.1@-2315,-1702.91 -2332.09,-1720 R54.1@-2500,-1720
NetC29_1: C29.1 U5.4 | length 95.4
  Top Layer w25.59: C29.1@-3427.76,2532.24 U5.4@-3427.76,2627.6
NetC39_2: C39.2 R8.1 R64.2 | length 259.5
  Top Layer w25: R64.2@-2420,1790 R8.1@-2420,1910 -2347.09,1910 C39.2@-2300,1957.09
NetC40_2: C40.2 R40.1 R66.2 | length 259.5
  Top Layer w25: R66.2@-2420,-760 R40.1@-2420,-640 -2347.09,-640 C40.2@-2300,-592.91
NetF1_1: F1.1 R1.2 TP3.1
  other v1: -2495,480 -2455,480 -2415,480 -2370,480 -2495,520 -2455,520 -2415,520 -2375,520
  other v2: -2336.63,438.36 -2296.29,438.36 -2495,440 -2455,440 -2415,440 -2375,440 -2331.64,478.71 -2291.29,478.71 -2336.64,519.05 -2296.29,520.43 -2336.64,559.4 -2296.29,559.4 -2338.41,599.51 -2298.19,600.47 -3455,1660 -3410,1660 -3355,1659.65 -3305,1659.65 -3455,1700 -3410,1700 -3355,1700 -3305,1700 -3355,1750 -3305,1750 -3210,1750 -3355,1800 -3305,1800 -3210,1830 -3355,1850 -3305,1850 -3455,1890 -3410,1890 -3355,1890.35 -3305,1890.35
NetF3_1: F3.1 R36.2 TP23.1 | length 219.8
  Top Layer w20: TP23.1@-2455,-2260 -2455,-2140 -2455,-2110 -2455,-2070 -2455,-2043.94 R36.2@-2452.36,-2041.3
  other v1: -2500,-2145 -2450,-2145 -2405,-2145 -2500,-2105 -2450,-2105 -2405,-2105 -2500,-2071.31 -2450,-2070 -2405,-2070 -2500,-2035 -2450,-2035 -2405,-2035 -2500,-2005 -2450,-2005 -2405,-2005
  other v2: -2455,-2300 -2455,-2220
NetJ4_2: J4.2 R30.1 | length 150
  Top Layer w25: J4.2@-3330,-390 R30.1@-3330,-240
NetL1_2: L1.2 R13.2 TP7.1
  other v1: 1695,710 1735,710 1775,710 1815,710 1855,710 1885,710 1695,745 1735,745 1775,745 1815,745 1855,745 1885,745 1695,785 1735,785 1775,785 1815,785 1855,785 1885,785
  other v2: 2145,755 2225,755
  other v3: 1620,875 1695,875 1770,875 1920,875 1995,875 2070,875 2145,875 2220,875 1845,879.13 1620,950 1695,950 1770,950 1845,950 1920,950 1995,950 2070,950 2145,950 2220,950 1620,1025 1695,1025 1770,1025 1845,1025 1920,1025 1995,1025 2070,1025 2145,1025 2220,1025 1620,1100 1695,1100 1770,1100 1845,1100 1920,1100 1995,1100 2070,1100 2145,1100 2220,1100 1620,1175 1695,1175 1770,1175 1845,1175 1920,1175 1995,1175 2070,1175 2145,1175 2220,1175 1620,1250 1695,1250 1770,1250 1845,1250 2145,1250 2220,1250 1620,1325 1695,1325 2220,1325
NetL2_1: L2.1 R44.1 TP29.1
  other v1: 1695,-785 1735,-785 1775,-785 1815,-785 1855,-785 1885,-785 1695,-750 1735,-750 1775,-750 1815,-750 1855,-750 1885,-750 1695,-710 1735,-710 1775,-710 1815,-710 1855,-710 1885,-710
  other v3: 1620,-1325 1695,-1325 2220,-1325 1620,-1250 1695,-1250 1770,-1250 2145,-1250 2220,-1250 1620,-1175 1695,-1175 1770,-1175 1845,-1175 1920,-1175 1995,-1175 2070,-1175 2145,-1175 2220,-1175 1620,-1100 1695,-1100 1770,-1100 1845,-1100 1920,-1100 1995,-1100 2070,-1100 2145,-1100 2220,-1100 1620,-1025 1695,-1025 1770,-1025 1845,-1025 1920,-1025 1995,-1025 2070,-1025 2145,-1025 2220,-1025 1620,-950 1695,-950 1770,-950 1845,-950 1920,-950 1995,-950 2070,-950 2145,-950 2220,-950 1695,-885 1770,-885 1845,-879.13 1920,-879.13 1995,-879.13 1620,-875 2070,-875 2145,-875 2220,-875
NetQ1_4: Q1.4 R4.2 | length 110.5
  Top Layer w25: Q1.4@175,1788.78 176.22,1790 R4.2@285,1790
NetQ2_4: Q2.4 R5.1 | length 110.5
  Top Layer w25: Q2.4@675,1788.78 676.22,1790 R5.1@785,1790
NetQ3_4: Q3.4 R6.1 | length 108.8
  Top Layer w25: Q3.4@1176.22,1790 R6.1@1285,1790
NetQ4_3: Q4.3 R3.1 | length 253.9
  Top Layer w15: Q4.3@-3783.5,-180 -3780,-180 -3755,-155 R3.1@-3540,-155
NetQ5_2: Q5.2 R11.2 | length 93.5
  Top Layer w20: Q5.2@-2717.24,1677.6 -2717.24,1587.24 R11.2@-2715,1585
NetQ5_3: Q5.3 R63.1 U1.2 | length 421.8
  Top Layer w20: Q5.3@-2622.76,1715 R63.1@-2535,1715 ; R63.1@-2530,1710 -2490,1670 -2490,1580 -2460,1550 U1.2@-2315,1550
NetQ6_4: Q6.4 R25.2 | length 110
  Top Layer w25: R25.2@-521.22,1380 Q6.4@-521.22,1490
NetQ7_4: Q7.4 R22.1 | length 116.6
  Top Layer w25: R22.1@-520,890 -520,1001.22 Q7.4@-516.22,1005
NetQ8_4: Q8.4 R23.1 | length 106.2
  Top Layer w25: Q8.4@178.78,685 R23.1@285,685
NetQ9_4: Q9.4 R21.1 | length 111.2
  Top Layer w25: Q9.4@678.78,685 R21.1@790,685
NetQ10_4: Q10.4 R24.1 | length 111.2
  Top Layer w25: Q10.4@1178.78,685 R24.1@1290,685
NetQ11_3: Q11.3 R17.1 | length 132.7
  Top Layer w20: R17.1@-3383.31,-995 -3383.31,-1080.98 -3359.28,-1105 Q11.3@-3346.5,-1105
NetQ12_2: Q12.2 R33.2 | length 93.7
  Top Layer w25: Q12.2@-2822.6,927.76 -2732.76,927.76 R33.2@-2730,925
NetQ13_4: Q13.4 R41.2 | length 108.8
  Top Layer w25: R41.2@-85,-1790 Q13.4@23.78,-1790
NetQ14_4: Q14.4 R37.1 | length 110.5
  Top Layer w25: R37.1@415,-1790 523.78,-1790 Q14.4@525,-1788.78
NetQ15_4: Q15.4 R38.1 | length 110.5
  Top Layer w25: R38.1@915,-1790 1023.78,-1790 Q15.4@1025,-1788.78
NetQ16_2: Q16.2 R42.2 | length 93.5
  Top Layer w25: Q16.2@-2717.24,-872.4 -2717.24,-962.76 R42.2@-2715,-965
NetQ16_3: Q16.3 R65.1 U4.2 | length 396.4
  Top Layer w25: Q16.3@-2622.76,-835 R65.1@-2535,-835 ; R65.1@-2530,-844 -2501.81,-872.19 -2501.81,-921.81 -2423.62,-1000 U4.2@-2315,-1000
NetQ17_4: Q17.4 R51.1 | length 108.8
  Top Layer w25: R51.1@-525,-1525 Q17.4@-525,-1416.22
NetQ18_4: Q18.4 R47.1 | length 110.5
  Top Layer w25: Q18.4@-526.22,-915 -526.22,-1023.78 R47.1@-525,-1025
NetQ19_4: Q19.4 R48.1 | length 108.8
  Top Layer w25: R48.1@-85,-690 Q19.4@23.78,-690
NetQ20_4: Q20.4 R49.1 | length 108.8
  Top Layer w25: R49.1@415,-690 Q20.4@523.78,-690
NetQ21_4: Q21.4 R50.1 | length 108.8
  Top Layer w25: R50.1@915,-690 Q21.4@1023.78,-690
NetQ22_2: Q22.2 R61.2 | length 93.7
  Top Layer w20: Q22.2@-2822.6,-1622.24 -2732.76,-1622.24 R61.2@-2730,-1625
NetR12_1: R12.1 U1.27 | length 275
  Top Layer w20: U1.27@-1945,1550 v2(-1865,1550) ; v2(-1725,1550) R12.1@-1670,1550
  MidLayer2 w20: v2(-1865,1550) v2(-1725,1550)
NetR15_1: R15.1 U1.24 | length 275
  Top Layer w20: U1.24@-1945,1400 v2(-1865,1400) ; v2(-1725,1400) R15.1@-1670,1400
  MidLayer2 w20: v2(-1865,1400) v2(-1725,1400)
NetR20_1: R20.1 U1.22 | length 270
  Top Layer w20: U1.22@-1945,1300 v2(-1865,1300) ; v2(-1725,1300) R20.1@-1675,1300
  MidLayer2 w20: v2(-1865,1300) v2(-1725,1300)
NetR26_1: R26.1 U1.19 | length 275
  Top Layer w20: U1.19@-1945,1150 v2(-1865,1150) ; v2(-1725,1150) R26.1@-1670,1150
  MidLayer2 w20: v2(-1865,1150) v2(-1725,1150)
NetR43_1: R43.1 U4.27 | length 275
  Top Layer w25: U4.27@-1945,-1000 v2(-1865,-1000) ; v2(-1725,-1000) R43.1@-1670,-1000
  MidLayer2 w25: v2(-1865,-1000) v2(-1725,-1000)
NetR45_1: R45.1 U4.24 | length 275
  Top Layer w25: U4.24@-1945,-1150 v2(-1865,-1150) ; v2(-1725,-1150) R45.1@-1670,-1150
  MidLayer2 w25: v2(-1865,-1150) v2(-1725,-1150)
NetR46_1: R46.1 U4.22 | length 275
  Top Layer w25: U4.22@-1945,-1250 v2(-1865,-1250) ; v2(-1725,-1250) R46.1@-1670,-1250
  MidLayer2 w25: v2(-1865,-1250) v2(-1725,-1250)
NetR52_1: R52.1 U4.19 | length 275
  Top Layer w25: U4.19@-1945,-1400 v2(-1865,-1400) ; v2(-1725,-1400) R52.1@-1670,-1400
  MidLayer2 w25: v2(-1865,-1400) v2(-1725,-1400)
NetR64_1: R64.1 U1.1 | length 265.7
  Top Layer w20: R64.1@-2420,1710 -2460,1670 -2460,1610 -2450,1600 U1.1@-2315,1600
NetR66_1: R66.1 U4.1 | length 210.4
  Top Layer w25: R66.1@-2450,-860 -2450,-926.38 -2425,-951.38 U4.1@-2316.38,-951.38
P1_HI: J3.9 TP20.1 U1.7 U1.8 | length 4447.9
  Top Layer w8: TP20.1@-4320,615 -4205.25,615 -4194.75,604.51 -4194.75,575 ; J3.9@-3730,-690 -3730,-700.63 -3804.37,-775 -4154.29,-775 -4318.25,-611.04 -4318.25,451.5 -4194.75,575 ; v2(-2475,1335) -3330,1335 -4090,575 -4194.75,575
  Top Layer w20: U1.8@-2315,1250 v2(-2400,1250) v2(-2400,1300) U1.7@-2315,1300
  MidLayer3 w8: J3.9@-3740,-690 J3.9@-3730,-690
  Bottom Layer w20: v2(-2475,1335) -2435,1335 v2(-2400,1300)
  other v2: -4360,615
P1_I48M: C18.1 J3.6 R34.2 TP16.1 U1.12 | length 3583.6
  Top Layer w20: v2(-2400,1050) U1.12@-2315,1050 -2265,1050 -2195,980 ; TP16.1@-2195,795 TP16.1@-2195,810 -2195,980 ; C18.1@-2095,750 -2095,845 -2095,880 -2195,980
  MidLayer4 w8: J3.6@-3530,-590 -3580,-540 -3580,-350 -3546.87,-316.87 -3386.13,-316.87 -3281.87,-316.87 -3225,-260 -2625,-260 -2220,145 -2220,1020 -2250,1050 v2(-2400,1050)
P1_LO: J3.11 TP24.1 U1.6 U1.9 | length 4278.3
  Top Layer w8: TP24.1@-4120,480 -4120,559 ; J3.11@-3830,-690 -3890,-750 -4140,-750 -4298.78,-591.22 -4298.78,441.22 -4181,559 -4120,559 ; -2435,1295 -3335.13,1295 -4071.13,559 -4120,559
  Top Layer w20: U1.9@-2315,1200 -2435,1200 -2435,1295 -2435,1350 v2(-2400,1350) U1.6@-2315,1350
  other v2: -4160,480 -4080,480
P2_HI: J4.13 TP26.1 U4.7 U4.8 | length 3017.1
  Top Layer w8: TP26.1@-4320,-1400 -4195,-1400 -4095,-1300 -3880,-1300 ; v2(-3880,-1250) -3880,-1300 ; v2(-2485,-1300) -3880,-1300
  Top Layer w25: U4.8@-2315,-1300 v2(-2400,-1300) v2(-2400,-1250) U4.7@-2315,-1250
  MidLayer3 w8: J4.13@-3935,-490 J4.13@-3930,-490
  MidLayer4 w8: J4.13@-3930,-490 -3880,-540 v2(-3880,-1250)
  Bottom Layer w25: v2@-2490,-1300 v2(-2485,-1300) v2@-2405,-1300
  other v2: -4360,-1400 -4280,-1400
P2_I48M: C13.1 J3.2 R27.2 TP12.1 U4.12 | length 2324.6
  Top Layer w8: J3.2@-3330,-590 -3235,-590 -3205,-620 R27.2@-3135,-620
  Top Layer w10: C13.1@-3030,-635 -2975,-635 -2935,-675 TP12.1@-2935,-865
  Top Layer w20: R27.2@-3135,-635 C13.1@-3030,-635 C13.1@-3045,-620 ; TP12.1@-2935,-865 TP12.1@-2930,-870 ; U4.12@-2315,-1500 v2(-2240,-1500)
  MidLayer4 w8: v2(-3080,-635) -3080,-670.89 -3040,-710.89 -3040,-990 -2925,-1105 -2280,-1105 -2220,-1165 -2220,-1480 v2(-2240,-1500)
P2_LOW: J4.11 TP25.1 U4.6 U4.9 | length 3094.6
  Top Layer w8: TP25.1@-4320,-1200 -3860,-1200 -3840,-1220 v2(-3835,-1220) -3835,-1245 -3810,-1270 -2441.38,-1270
  Top Layer w25: U4.9@-2315,-1350 v2(-2400,-1350) -2441.38,-1350 -2441.38,-1270 -2441.38,-1215.16 -2426.22,-1200 v2(-2400,-1200) U4.6@-2315,-1200
  MidLayer3 w8: J4.11@-3830,-495 J4.11@-3830,-490
  MidLayer4 w8: v2(-3835,-1220) -3835,-910 -3780,-855 -3780,-540 J4.11@-3830,-490
  other v2: -4360,-1200 -4280,-1200
PGOOD_P1: J4.9 TP21.1 U1.10 | length 3329.4
  Top Layer w20: TP21.1@-2600,1130 -2481.9,1130 -2461.9,1150 v2(-2400,1150) U1.10@-2315,1150
  MidLayer4 w8: v2(-3110,-295) -2630,-295 -2200,135 -2200,1065 -2285,1150 v2(-2400,1150)
  Bottom Layer w8: J4.9@-3730,-490 -3680,-440 -3680,-345 -3598.12,-263.12 -3340.87,-263.12 -3308.99,-295 v2(-3110,-295)
PGOOD_P2: J4.5 TP17.1 U4.10 | length 2674.5
  Top Layer w8: J4.5@-3530,-490 -3480,-540 -3395,-540 -3380.63,-554.37 -3380.63,-724.37 -2955,-1150 -2710,-1150 -2622.5,-1240 v2@-2552.5,-1240 ; v2@-2552.5,-1237.5 v2(-2550,-1240)
  Top Layer w25: TP17.1@-2540,-1400 v2(-2400,-1400) U4.10@-2315,-1400
  MidLayer2 w10: v2@-2550,-1245 -2550,-1370 -2520,-1400 v2(-2400,-1400)
  Bottom Layer w25: v2(-3170,-1400) v2(-2400,-1400)
SCL: J3.5 R9.2 R18.2 U2.B2 U3.B2 | length 14479.3
  Top Layer w8: U2.B2@1340,1982.13 1340,1970 1369.92,1940.08 v2(1382.95,1940.08) ; U3.B2@1347.87,-2007.87 1347.87,-2032.87 1355,-2040 v2(1375,-2040)
  Top Layer w10: v2(-3595,-1105) -3595,-967.79 -3530,-902.79 J3.5@-3530,-690 J3.5@-3530,-685
  Top Layer w20: R9.2@-3660,-1205 R18.2@-3660,-1105 v2(-3595,-1105)
  MidLayer4 w10: v2(-3595,-1105) -3595,-2480 -3500,-2575 1205,-2575 1375,-2405 1375,-2180 ; v2(1375,-2040) 1375,-2180 ; v2(1382.95,1940.08) 1385.08,1940.08 1660,2215 2555,2215 2735,2035 2735,-1855 2410,-2180 1375,-2180
SDA: J3.7 R10.2 R19.2 U2.B1 U3.B1 | length 14418
  Top Layer w8: v2(1305,-2040) 1325,-2040 1332.13,-2032.87 U3.B1@1332.13,-2007.87 ; v2(1322.95,1940.08) v2@1324.25,1941.38 ; U2.B1@1324.25,1982.13 v2@1324.25,1941.38 ; v2@1325.08,1942.2 v2@1324.25,1941.38
  Top Layer w10: J3.7@-3630,-690 -3630,-795 -3595,-830 v2(-3594.26,-901.27)
  Top Layer w20: R10.2@-3660,-1005 R19.2@-3660,-905 ; R19.2@-3654.26,-901.27 v2(-3594.26,-901.27)
  MidLayer4 w8: v2(1322.95,1940.08) v2@1324.92,1940.08
  MidLayer4 w10: v2(-3594.26,-901.27) -3595,-1005 -3560,-1040 -3560,-2470 -3485,-2545 1170,-2545 1305,-2410 v2(1305,-2040) 1305,-2030.08 1330.08,-2005 1400,-2005 1545,-2150 2395,-2150 2700,-1845 2700,1985 2500,2185 1685,2185 1400,1900 1363.03,1900 v2(1322.95,1940.08)
SIAP1_N: R7.2 R13.3 | length 10121.3
  Top Layer w25: R7.2@-2530,1990 v2(-2530,2055) ; v2(1575,625) 1610,625 1623.7,611.3 R13.3@1623.7,552.36
  MidLayer2 w25: v2(-2530,2055) -2492.5,2017.5 -2492.5,1968 -2439.75,1915.25 -2354.75,1915.25 -2280,1990 -2280,2655 -2065,2870 2635.5,2870 2795,2710.5 2795,595 2680,480 1500,480 1485,495 1485,585 1530,630 1570,630 v2(1575,625)
SIAP1_P: R8.2 R13.4 | length 10301.1
  Top Layer w25: R8.2@-2420,1990 v2(-2420,2055) ; v2(1575,670) 1611.42,670 1623.5,682.09 R13.4@1623.5,747.64
  MidLayer2 w25: v2(-2420,2055) -2457.5,2017.5 -2457.5,1982.5 -2425.25,1950.25 -2369.25,1950.25 -2315,2004.5 -2315,2669.5 -2079.5,2905 2650,2905 2830,2725 2830,580.5 2694.5,445 1485.5,445 1450,480.5 1450,599.5 1515.5,665 1570,665 v2(1575,670)
SIAP2_N: R39.2 R44.4 | length 4714
  Top Layer w20: R39.2@-2530,-560 v2(-2530,-480)
  Top Layer w25: v2(1575,-625) 1616.42,-625 1623.5,-617.91 R44.4@1623.5,-552.36
  MidLayer2 w25: v2(-2530,-480) -2515.23,-480 -2492.57,-457.34 -2492.57,-430.2 -2177.37,-115 -300.5,-115 34.5,-450 1325,-450 1505,-630 1547.5,-630 ; 1547.5,-630 1548.5,-629 v2@1561,-629 ; 1547.5,-630 1560,-630 v2@1561,-629 ; v2@1561,-629 1571,-629 v2(1575,-625) 1565,-625 v2@1561,-629
SIAP2_P: R40.2 R44.3 | length 4652.5
  Top Layer w20: R40.2@-2420,-560 v2(-2420,-480)
  Top Layer w25: v2(1575,-670) 1616.42,-670 1623.7,-677.28 R44.3@1623.7,-747.64
  MidLayer2 w25: v2(-2420,-480) -2445.73,-480 -2457.57,-468.16 -2457.57,-444.7 -2162.87,-150 -315,-150 20,-485 1310.5,-485 1490.5,-665 v2@1564,-665 ; v2@1563,-664 v2@1564,-665 ; v2@1564,-665 1569,-670 v2(1575,-670) 1570,-665 v2@1564,-665
SIB: R29.1 U1.14 | length 105
  Top Layer w20: R29.1@-2420,950 U1.14@-2315,950
SIB2: R55.1 U4.14 | length 105
  Top Layer w20: R55.1@-2420,-1600 U4.14@-2315,-1600
SOB: C16.1 Q12.3 R32.1 U1.13 | length 885.5
  Top Layer w20: Q12.3@-2860,1022.24 -2847.24,1035 -2570,1035 -2550,1015 -2550,1000 ; C16.1@-2730,830 R32.1@-2615,830 -2615,870 -2550,935 -2550,1000 ; U1.13@-2315,1000 -2550,1000
SOB2: C32.1 Q22.3 R57.1 U4.13 | length 888
  Top Layer w20: Q22.3@-2860,-1527.76 -2847.24,-1515 -2565,-1515 -2547.5,-1532.5 -2547.5,-1550 ; C32.1@-2730,-1720 R57.1@-2615,-1720 -2547.5,-1652.5 -2547.5,-1550 ; U4.13@-2315,-1550 -2547.5,-1550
